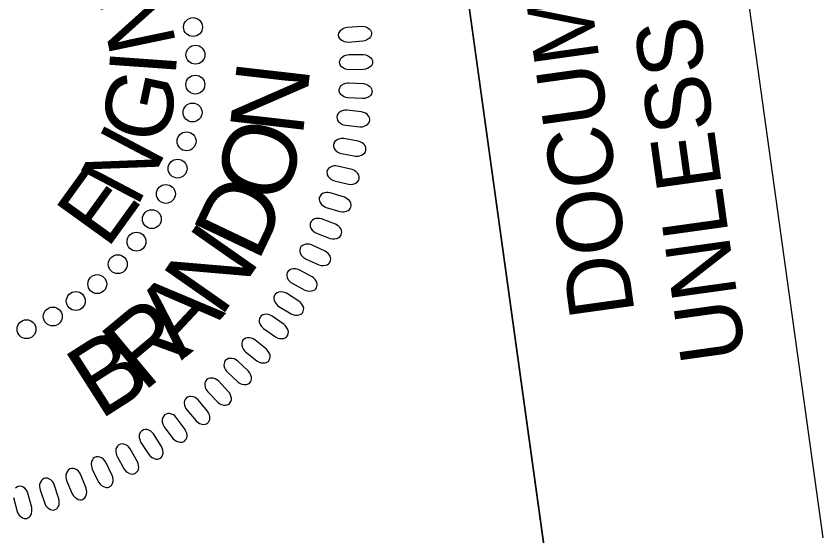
# Model space of a CAD drawing. Extents: x 477288 to 478604, y 497629 to 499448.
# Drawn here: x 477443.3 to 477511.7, y 499108.8 to 499152.9 of the extents above; entities that cross this region are included whole.
import ezdxf

# ---------------------------------------------------------------- set-up
doc = ezdxf.new("R2010")
doc.units = 0
for name, color, linetype in [('Sheet PE Seal Cell', 7, 'Continuous'), ('Sheet Plan CELL', 7, 'Continuous'), ('Sheet Sticker Exception Certification CELL', 7, 'Continuous')]:
    doc.layers.add(name, color=color, linetype=linetype)

msp = doc.modelspace()

# ---------------------------------------------------------------- linework, layer by layer
at = {"layer": 'Sheet PE Seal Cell'}
for points in [[(477471.352, 499151.931), (477472.575, 499152.022), (477472.796, 499152.002), (477472.94, 499151.96), (477473.118, 499151.861), (477473.235, 499151.773), (477473.322, 499151.667), (477473.37, 499151.565), (477473.398, 499151.454), (477473.386, 499151.342), (477473.366, 499151.22), (477473.314, 499151.112), (477473.222, 499151), (477473.147, 499150.933), (477473.003, 499150.855), (477472.829, 499150.782), (477472.671, 499150.748), (477471.419, 499150.646), (477471.248, 499150.656), (477471.105, 499150.69), (477470.94, 499150.768), (477470.792, 499150.868), (477470.705, 499150.96), (477470.634, 499151.112), (477470.603, 499151.26), (477470.631, 499151.412), (477470.673, 499151.519), (477470.763, 499151.654), (477470.923, 499151.785), (477471.097, 499151.867), (477471.224, 499151.905)], [(477471.476, 499149.608), (477472.702, 499149.623), (477472.922, 499149.588), (477473.063, 499149.538), (477473.234, 499149.428), (477473.344, 499149.332), (477473.426, 499149.221), (477473.467, 499149.117), (477473.488, 499149.005), (477473.469, 499148.893), (477473.441, 499148.772), (477473.383, 499148.667), (477473.284, 499148.562), (477473.205, 499148.5), (477473.056, 499148.432), (477472.877, 499148.369), (477472.718, 499148.345), (477471.462, 499148.322), (477471.292, 499148.342), (477471.152, 499148.386), (477470.991, 499148.473), (477470.85, 499148.584), (477470.769, 499148.68), (477470.707, 499148.836), (477470.686, 499148.986), (477470.724, 499149.135), (477470.772, 499149.241), (477470.87, 499149.369), (477471.038, 499149.49), (477471.217, 499149.56), (477471.347, 499149.591)], [(477471.479, 499147.22), (477472.704, 499147.157), (477472.921, 499147.109), (477473.058, 499147.05), (477473.222, 499146.929), (477473.326, 499146.827), (477473.4, 499146.711), (477473.435, 499146.604), (477473.449, 499146.491), (477473.423, 499146.381), (477473.388, 499146.262), (477473.323, 499146.161), (477473.218, 499146.062), (477473.135, 499146.006), (477472.982, 499145.946), (477472.8, 499145.895), (477472.639, 499145.881), (477471.384, 499145.937), (477471.216, 499145.968), (477471.079, 499146.02), (477470.924, 499146.118), (477470.79, 499146.237), (477470.715, 499146.338), (477470.664, 499146.497), (477470.651, 499146.648), (477470.699, 499146.795), (477470.754, 499146.897), (477470.859, 499147.019), (477471.035, 499147.129), (477471.218, 499147.188), (477471.348, 499147.211)], [(477471.184, 499143.623), (477472.403, 499143.484), (477472.624, 499143.496), (477472.77, 499143.532), (477472.951, 499143.625), (477473.071, 499143.708), (477473.163, 499143.811), (477473.215, 499143.91), (477473.247, 499144.02), (477473.239, 499144.133), (477473.223, 499144.256), (477473.176, 499144.366), (477473.089, 499144.481), (477473.017, 499144.55), (477472.875, 499144.633), (477472.703, 499144.713), (477472.547, 499144.754), (477471.3, 499144.904), (477471.129, 499144.9), (477470.985, 499144.871), (477470.816, 499144.8), (477470.665, 499144.705), (477470.575, 499144.617), (477470.497, 499144.468), (477470.461, 499144.322), (477470.484, 499144.168), (477470.522, 499144.059), (477470.606, 499143.921), (477470.761, 499143.784), (477470.932, 499143.696), (477471.057, 499143.652)], [(477470.839, 499141.219), (477472.047, 499141.004), (477472.27, 499141.003), (477472.416, 499141.029), (477472.603, 499141.11), (477472.728, 499141.186), (477472.826, 499141.284), (477472.883, 499141.379), (477472.923, 499141.486), (477472.923, 499141.6), (477472.914, 499141.723), (477472.874, 499141.837), (477472.793, 499141.957), (477472.726, 499142.03), (477472.59, 499142.122), (477472.424, 499142.212), (477472.271, 499142.263), (477471.035, 499142.491), (477470.864, 499142.498), (477470.719, 499142.478), (477470.546, 499142.418), (477470.389, 499142.332), (477470.293, 499142.25), (477470.207, 499142.106), (477470.161, 499141.962), (477470.174, 499141.808), (477470.206, 499141.697), (477470.281, 499141.554), (477470.427, 499141.407), (477470.592, 499141.309), (477470.714, 499141.257)], [(477470.25, 499138.907), (477471.442, 499138.617), (477471.664, 499138.601), (477471.812, 499138.619), (477472.004, 499138.688), (477472.133, 499138.756), (477472.237, 499138.846), (477472.301, 499138.938), (477472.347, 499139.043), (477472.353, 499139.156), (477472.353, 499139.28), (477472.32, 499139.395), (477472.247, 499139.521), (477472.184, 499139.598), (477472.055, 499139.698), (477471.895, 499139.799), (477471.745, 499139.859), (477470.525, 499140.163), (477470.356, 499140.182), (477470.21, 499140.171), (477470.033, 499140.122), (477469.871, 499140.046), (477469.77, 499139.97), (477469.675, 499139.832), (477469.62, 499139.691), (477469.624, 499139.537), (477469.648, 499139.423), (477469.714, 499139.276), (477469.851, 499139.12), (477470.01, 499139.012), (477470.128, 499138.953)], [(477469.545, 499136.661), (477470.716, 499136.297), (477470.936, 499136.267), (477471.085, 499136.275), (477471.281, 499136.332), (477471.414, 499136.392), (477471.524, 499136.475), (477471.593, 499136.563), (477471.645, 499136.665), (477471.659, 499136.778), (477471.667, 499136.901), (477471.641, 499137.018), (477471.576, 499137.148), (477471.518, 499137.229), (477471.395, 499137.338), (477471.242, 499137.448), (477471.096, 499137.517), (477469.899, 499137.898), (477469.729, 499137.927), (477469.583, 499137.925), (477469.404, 499137.888), (477469.237, 499137.822), (477469.132, 499137.752), (477469.029, 499137.62), (477468.965, 499137.483), (477468.959, 499137.329), (477468.975, 499137.214), (477469.032, 499137.063), (477469.159, 499136.899), (477469.311, 499136.781), (477469.425, 499136.714)], [(477468.733, 499134.469), (477469.879, 499134.031), (477470.097, 499133.988), (477470.246, 499133.987), (477470.444, 499134.031), (477470.582, 499134.083), (477470.696, 499134.159), (477470.771, 499134.242), (477470.83, 499134.341), (477470.85, 499134.452), (477470.866, 499134.574), (477470.847, 499134.694), (477470.791, 499134.827), (477470.738, 499134.911), (477470.622, 499135.028), (477470.476, 499135.148), (477470.335, 499135.226), (477469.163, 499135.68), (477468.997, 499135.72), (477468.85, 499135.728), (477468.669, 499135.701), (477468.499, 499135.646), (477468.39, 499135.584), (477468.278, 499135.458), (477468.206, 499135.326), (477468.19, 499135.172), (477468.199, 499135.056), (477468.247, 499134.902), (477468.363, 499134.73), (477468.507, 499134.603), (477468.617, 499134.529)], [(477467.807, 499132.303), (477468.924, 499131.794), (477469.138, 499131.737), (477469.287, 499131.727), (477469.488, 499131.758), (477469.628, 499131.801), (477469.747, 499131.87), (477469.827, 499131.948), (477469.891, 499132.043), (477469.92, 499132.153), (477469.943, 499132.274), (477469.931, 499132.394), (477469.884, 499132.531), (477469.836, 499132.619), (477469.728, 499132.742), (477469.589, 499132.87), (477469.453, 499132.957), (477468.313, 499133.485), (477468.149, 499133.534), (477468.004, 499133.551), (477467.821, 499133.536), (477467.648, 499133.492), (477467.535, 499133.436), (477467.415, 499133.319), (477467.335, 499133.191), (477467.31, 499133.038), (477467.312, 499132.922), (477467.349, 499132.766), (477467.454, 499132.587), (477467.59, 499132.45), (477467.695, 499132.37)], [(477466.669, 499130.224), (477467.752, 499129.647), (477467.963, 499129.576), (477468.111, 499129.557), (477468.313, 499129.575), (477468.456, 499129.61), (477468.579, 499129.671), (477468.663, 499129.744), (477468.734, 499129.834), (477468.769, 499129.942), (477468.798, 499130.062), (477468.796, 499130.183), (477468.756, 499130.322), (477468.715, 499130.412), (477468.614, 499130.542), (477468.484, 499130.679), (477468.354, 499130.774), (477467.249, 499131.372), (477467.089, 499131.433), (477466.944, 499131.459), (477466.762, 499131.455), (477466.585, 499131.422), (477466.469, 499131.374), (477466.342, 499131.264), (477466.254, 499131.141), (477466.219, 499130.99), (477466.214, 499130.874), (477466.242, 499130.715), (477466.336, 499130.53), (477466.462, 499130.386), (477466.563, 499130.299)], [(477465.527, 499128.267), (477466.572, 499127.622), (477466.778, 499127.539), (477466.924, 499127.51), (477467.127, 499127.516), (477467.272, 499127.542), (477467.399, 499127.595), (477467.488, 499127.663), (477467.564, 499127.748), (477467.605, 499127.853), (477467.642, 499127.971), (477467.647, 499128.091), (477467.616, 499128.234), (477467.581, 499128.326), (477467.489, 499128.462), (477467.367, 499128.607), (477467.243, 499128.71), (477466.178, 499129.377), (477466.022, 499129.447), (477465.879, 499129.481), (477465.697, 499129.489), (477465.519, 499129.468), (477465.399, 499129.427), (477465.267, 499129.324), (477465.171, 499129.208), (477465.127, 499129.06), (477465.114, 499128.944), (477465.132, 499128.784), (477465.214, 499128.593), (477465.331, 499128.441), (477465.425, 499128.348)], [(477464.245, 499126.383), (477465.246, 499125.674), (477465.447, 499125.577), (477465.591, 499125.54), (477465.794, 499125.533), (477465.941, 499125.549), (477466.07, 499125.594), (477466.162, 499125.657), (477466.244, 499125.737), (477466.292, 499125.839), (477466.337, 499125.955), (477466.349, 499126.075), (477466.327, 499126.218), (477466.297, 499126.312), (477466.214, 499126.454), (477466.102, 499126.606), (477465.985, 499126.717), (477464.963, 499127.449), (477464.812, 499127.529), (477464.672, 499127.573), (477464.49, 499127.592), (477464.312, 499127.581), (477464.19, 499127.548), (477464.051, 499127.455), (477463.948, 499127.343), (477463.894, 499127.198), (477463.875, 499127.084), (477463.882, 499126.923), (477463.952, 499126.728), (477464.06, 499126.568), (477464.148, 499126.469)], [(477462.723, 499124.419), (477463.678, 499123.648), (477463.871, 499123.54), (477464.013, 499123.492), (477464.216, 499123.473), (477464.362, 499123.48), (477464.495, 499123.517), (477464.592, 499123.574), (477464.677, 499123.649), (477464.732, 499123.749), (477464.784, 499123.861), (477464.803, 499123.979), (477464.791, 499124.123), (477464.767, 499124.22), (477464.692, 499124.367), (477464.59, 499124.526), (477464.481, 499124.643), (477463.507, 499125.438), (477463.361, 499125.527), (477463.224, 499125.579), (477463.044, 499125.61), (477462.865, 499125.611), (477462.742, 499125.585), (477462.596, 499125.501), (477462.487, 499125.396), (477462.424, 499125.255), (477462.397, 499125.142), (477462.395, 499124.981), (477462.452, 499124.781), (477462.55, 499124.616), (477462.632, 499124.512)], [(477461.177, 499122.679), (477462.082, 499121.85), (477462.269, 499121.73), (477462.407, 499121.673), (477462.608, 499121.642), (477462.754, 499121.639), (477462.889, 499121.668), (477462.989, 499121.718), (477463.08, 499121.788), (477463.14, 499121.884), (477463.199, 499121.992), (477463.226, 499122.109), (477463.223, 499122.254), (477463.204, 499122.352), (477463.14, 499122.503), (477463.047, 499122.668), (477462.946, 499122.792), (477462.024, 499123.647), (477461.884, 499123.745), (477461.75, 499123.806), (477461.572, 499123.848), (477461.393, 499123.86), (477461.269, 499123.842), (477461.119, 499123.767), (477461.003, 499123.67), (477460.932, 499123.533), (477460.898, 499123.422), (477460.885, 499123.26), (477460.929, 499123.058), (477461.016, 499122.886), (477461.092, 499122.777)], [(477459.507, 499121.03), (477460.358, 499120.145), (477460.537, 499120.014), (477460.671, 499119.948), (477460.87, 499119.905), (477461.016, 499119.893), (477461.152, 499119.913), (477461.255, 499119.957), (477461.351, 499120.02), (477461.417, 499120.112), (477461.482, 499120.217), (477461.517, 499120.333), (477461.522, 499120.477), (477461.51, 499120.576), (477461.455, 499120.731), (477461.374, 499120.901), (477461.28, 499121.032), (477460.413, 499121.942), (477460.279, 499122.049), (477460.15, 499122.118), (477459.975, 499122.171), (477459.798, 499122.194), (477459.672, 499122.184), (477459.517, 499122.119), (477459.396, 499122.029), (477459.316, 499121.897), (477459.275, 499121.788), (477459.252, 499121.628), (477459.284, 499121.423), (477459.36, 499121.247), (477459.428, 499121.133)], [(477457.727, 499119.493), (477458.521, 499118.557), (477458.691, 499118.414), (477458.821, 499118.341), (477459.017, 499118.285), (477459.161, 499118.264), (477459.299, 499118.276), (477459.404, 499118.313), (477459.503, 499118.37), (477459.575, 499118.458), (477459.647, 499118.558), (477459.688, 499118.672), (477459.703, 499118.815), (477459.698, 499118.914), (477459.652, 499119.073), (477459.581, 499119.248), (477459.496, 499119.384), (477458.689, 499120.347), (477458.562, 499120.462), (477458.436, 499120.539), (477458.266, 499120.603), (477458.09, 499120.637), (477457.964, 499120.635), (477457.805, 499120.579), (477457.679, 499120.498), (477457.59, 499120.371), (477457.543, 499120.265), (477457.51, 499120.106), (477457.529, 499119.9), (477457.594, 499119.719), (477457.655, 499119.601)], [(477455.832, 499118.062), (477456.565, 499117.078), (477456.726, 499116.925), (477456.851, 499116.844), (477457.042, 499116.775), (477457.187, 499116.745), (477457.324, 499116.748), (477457.431, 499116.779), (477457.533, 499116.83), (477457.611, 499116.913), (477457.689, 499117.009), (477457.737, 499117.119), (477457.761, 499117.262), (477457.762, 499117.361), (477457.726, 499117.521), (477457.667, 499117.701), (477457.59, 499117.842), (477456.845, 499118.854), (477456.725, 499118.977), (477456.605, 499119.061), (477456.439, 499119.136), (477456.266, 499119.181), (477456.139, 499119.187), (477455.978, 499119.141), (477455.846, 499119.067), (477455.75, 499118.946), (477455.696, 499118.844), (477455.654, 499118.688), (477455.66, 499118.48), (477455.713, 499118.296), (477455.766, 499118.174)], [(477453.848, 499116.728), (477454.518, 499115.7), (477454.669, 499115.537), (477454.789, 499115.448), (477454.976, 499115.368), (477455.117, 499115.329), (477455.255, 499115.324), (477455.364, 499115.347), (477455.469, 499115.392), (477455.551, 499115.47), (477455.636, 499115.561), (477455.691, 499115.667), (477455.723, 499115.808), (477455.731, 499115.908), (477455.705, 499116.07), (477455.657, 499116.253), (477455.589, 499116.399), (477454.909, 499117.456), (477454.797, 499117.585), (477454.684, 499117.678), (477454.522, 499117.762), (477454.351, 499117.819), (477454.226, 499117.832), (477454.062, 499117.796), (477453.925, 499117.731), (477453.822, 499117.616), (477453.762, 499117.517), (477453.709, 499117.364), (477453.703, 499117.157), (477453.744, 499116.97), (477453.79, 499116.845)], [(477451.833, 499115.54), (477452.437, 499114.472), (477452.578, 499114.299), (477452.692, 499114.203), (477452.873, 499114.111), (477453.012, 499114.063), (477453.149, 499114.049), (477453.259, 499114.066), (477453.367, 499114.104), (477453.454, 499114.176), (477453.544, 499114.261), (477453.605, 499114.364), (477453.647, 499114.503), (477453.66, 499114.602), (477453.645, 499114.766), (477453.608, 499114.951), (477453.55, 499115.101), (477452.938, 499116.198), (477452.834, 499116.335), (477452.726, 499116.434), (477452.57, 499116.529), (477452.404, 499116.595), (477452.28, 499116.617), (477452.113, 499116.592), (477451.973, 499116.535), (477451.863, 499116.427), (477451.797, 499116.332), (477451.735, 499116.183), (477451.715, 499115.976), (477451.744, 499115.787), (477451.783, 499115.66)], [(477449.722, 499114.48), (477450.258, 499113.376), (477450.387, 499113.195), (477450.495, 499113.092), (477450.67, 499112.989), (477450.806, 499112.932), (477450.941, 499112.91), (477451.053, 499112.92), (477451.162, 499112.951), (477451.254, 499113.018), (477451.349, 499113.097), (477451.417, 499113.196), (477451.467, 499113.332), (477451.487, 499113.429), (477451.482, 499113.593), (477451.457, 499113.781), (477451.407, 499113.935), (477450.865, 499115.068), (477450.771, 499115.211), (477450.669, 499115.317), (477450.519, 499115.421), (477450.358, 499115.498), (477450.235, 499115.527), (477450.068, 499115.512), (477449.924, 499115.465), (477449.808, 499115.364), (477449.735, 499115.273), (477449.664, 499115.128), (477449.631, 499114.923), (477449.649, 499114.732), (477449.679, 499114.603)], [(477447.55, 499113.517), (477448.015, 499112.382), (477448.133, 499112.194), (477448.234, 499112.084), (477448.403, 499111.97), (477448.534, 499111.905), (477448.669, 499111.874), (477448.78, 499111.877), (477448.892, 499111.901), (477448.987, 499111.962), (477449.087, 499112.035), (477449.161, 499112.13), (477449.22, 499112.262), (477449.245, 499112.359), (477449.251, 499112.522), (477449.238, 499112.711), (477449.198, 499112.867), (477448.728, 499114.033), (477448.643, 499114.181), (477448.548, 499114.293), (477448.405, 499114.407), (477448.248, 499114.494), (477448.129, 499114.53), (477447.96, 499114.526), (477447.814, 499114.488), (477447.691, 499114.394), (477447.613, 499114.308), (477447.533, 499114.168), (477447.487, 499113.966), (477447.493, 499113.774), (477447.515, 499113.643)], [(477445.297, 499112.72), (477445.691, 499111.558), (477445.796, 499111.362), (477445.89, 499111.246), (477446.052, 499111.121), (477446.179, 499111.049), (477446.31, 499111.009), (477446.422, 499111.005), (477446.535, 499111.022), (477446.634, 499111.077), (477446.738, 499111.144), (477446.818, 499111.234), (477446.885, 499111.362), (477446.916, 499111.457), (477446.932, 499111.62), (477446.931, 499111.809), (477446.901, 499111.967), (477446.505, 499113.16), (477446.43, 499113.313), (477446.342, 499113.431), (477446.207, 499113.553), (477446.055, 499113.65), (477445.938, 499113.694), (477445.77, 499113.701), (477445.621, 499113.672), (477445.493, 499113.586), (477445.41, 499113.505), (477445.322, 499113.37), (477445.263, 499113.171), (477445.256, 499112.979), (477445.27, 499112.847)]]:
    msp.add_lwpolyline(points, close=True, dxfattribs=at)
msp.add_lwpolyline([(477443.04, 499112.069), (477443.359, 499110.884), (477443.453, 499110.683), (477443.539, 499110.561), (477443.692, 499110.427), (477443.815, 499110.346), (477443.944, 499110.298), (477444.055, 499110.287), (477444.169, 499110.297), (477444.271, 499110.346), (477444.379, 499110.406), (477444.465, 499110.49), (477444.54, 499110.614), (477444.577, 499110.707), (477444.603, 499110.868), (477444.614, 499111.058), (477444.594, 499111.217), (477444.274, 499112.433), (477444.208, 499112.59), (477444.128, 499112.714), (477444, 499112.844), (477443.856, 499112.95), (477443.741, 499113.002), (477443.573, 499113.019), (477443.424, 499112.999), (477443.29, 499112.921), (477443.202, 499112.846)], dxfattribs=at)
for centre in [(477458.265, 499151.942), (477458.47, 499149.599), (477458.46, 499147.065), (477458.225, 499144.701), (477457.719, 499142.259), (477456.955, 499139.943), (477455.966, 499137.796), (477454.774, 499135.661), (477453.471, 499133.751), (477451.886, 499131.843), (477450.149, 499130.155), (477448.326, 499128.721), (477446.377, 499127.405), (477444.153, 499126.333)]:
    msp.add_circle(centre, 0.801, dxfattribs=at)
at = {"layer": 'Sheet Plan CELL'}
msp.add_lwpolyline([(477376.966, 499089.904), (477363.175, 499188.999), (477474.614, 499204.507), (477488.378, 499105.421)], close=True, dxfattribs=at)
at = {"layer": 'Sheet Sticker Exception Certification CELL'}
for p, q in [((477484.081, 499306.788), (477511.654, 499108.66)), ((477484.081, 499306.788), (477511.654, 499108.66)), ((477488.378, 499105.421), (477460.805, 499303.549)), ((477488.378, 499105.421), (477460.805, 499303.549))]:
    msp.add_line(p, q, dxfattribs=at)

# ---------------------------------------------------------------- texts
at = {"layer": 'Sheet PE Seal Cell'}
for s, height, rotation, p in [('N', 5.669, 101.82705, (477456.868, 499150.439)), ('I', 5.669, 85.94746, (477456.779, 499147.647)), ('N', 6.236, 83.47319, (477467.551, 499142.566)), ('G', 5.669, 78.00766, (477455.881, 499141.839)), ('O', 6.236, 73.37334, (477465.967, 499136.74)), ('N', 5.669, 62.12806, (477453.487, 499136.565)), ('E', 5.669, 54.18827, (477450.992, 499133.052)), ('D', 6.236, 64.50511, (477463.752, 499131.923)), ('N', 6.236, 55.01542, (477460.59, 499127.212)), ('A', 6.236, 46.90425, (477457.302, 499123.646)), ('R', 6.236, 39.78741, (477454.028, 499120.926)), ('B', 6.236, 32.51238, (477450.359, 499118.587))]:
    msp.add_text(s, height=height, rotation=rotation, dxfattribs=at).set_placement(p)
at = {"layer": 'Sheet Sticker Exception Certification CELL'}
for s, p in [('UNLESS ALL SIGNATURES COMPLETED', (477505.135, 499123.907)), ('UNLESS ALL SIGNATURES COMPLETED', (477505.135, 499123.907)), ('DOCUMENT NOT CONSIDERED FINAL', (477495.72, 499127.717)), ('DOCUMENT NOT CONSIDERED FINAL', (477495.72, 499127.717))]:
    msp.add_text(s, height=5.5, rotation=97.92268, dxfattribs=at).set_placement(p)

doc.saveas('drawing.dxf')
